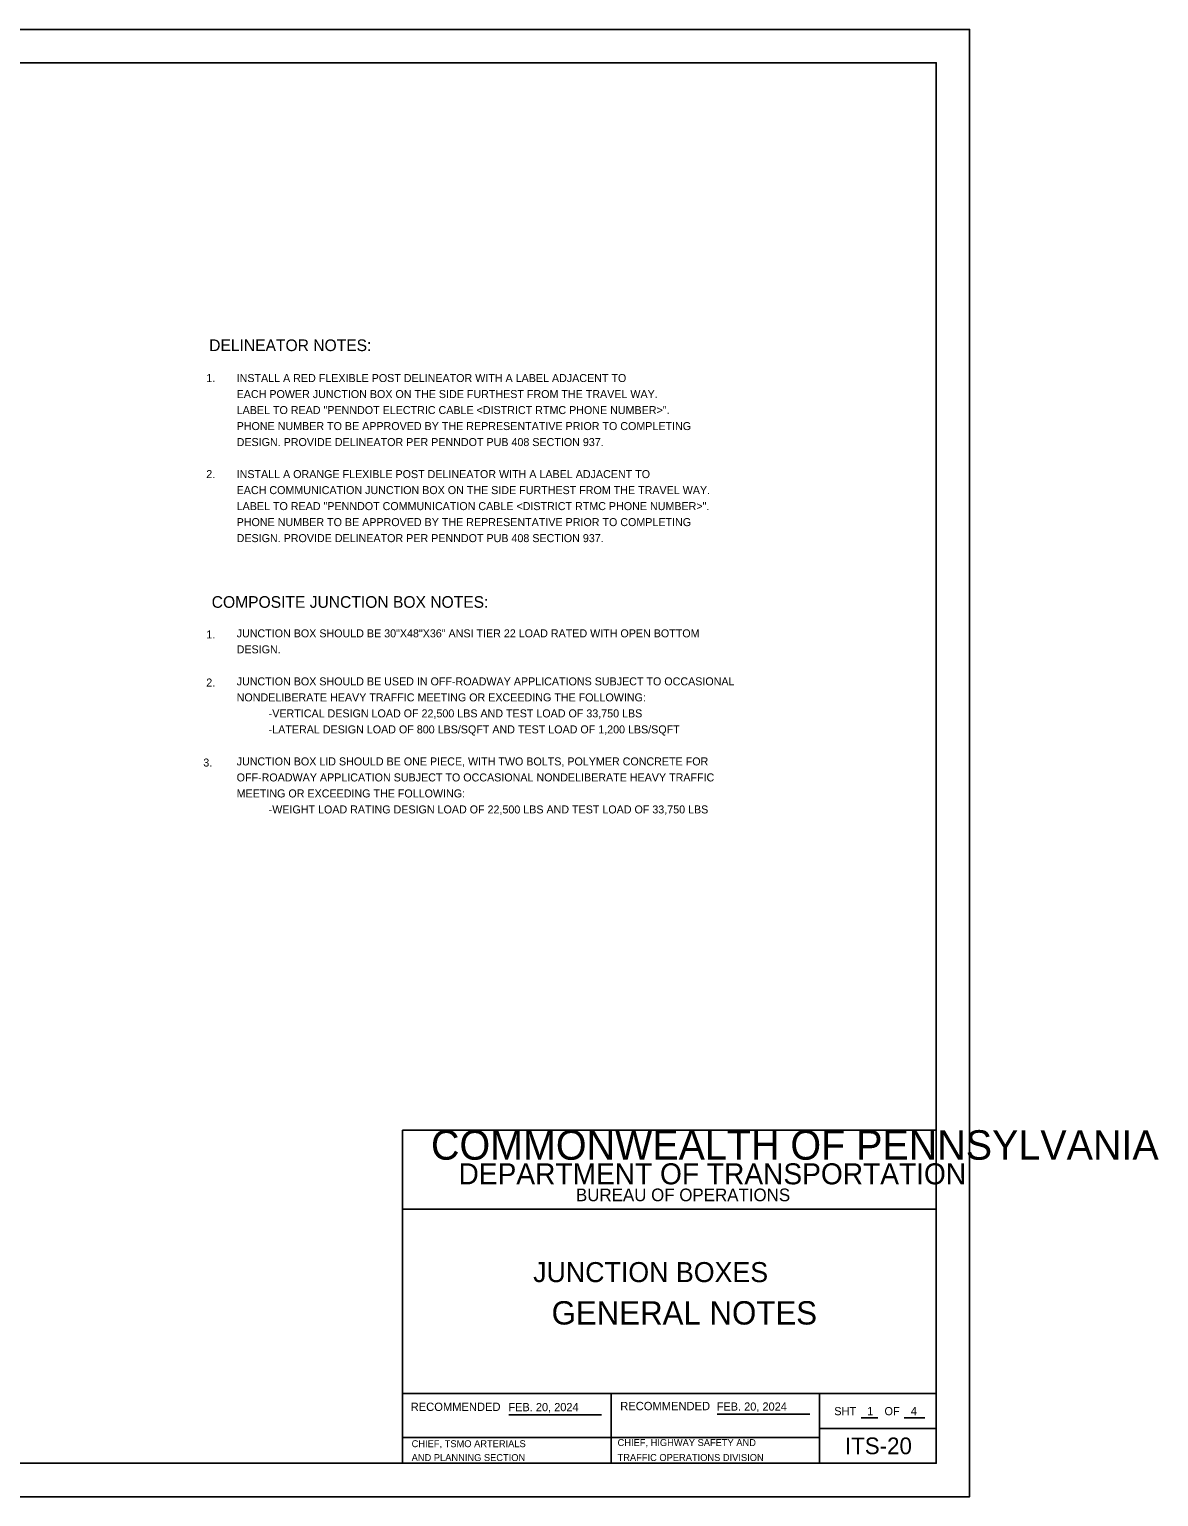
# Model space of a CAD drawing. Extents: x 1299104.8 to 1299141.6, y 239639.8 to 239661.8.
# Drawn here: x 1299124.71 to 1299141.64, y 239639.79 to 239661.79 of the extents above; entities that cross this region are included whole.
import ezdxf

# ---------------------------------------------------------------- set-up
doc = ezdxf.new("R2010")
doc.units = 0
for name, color, linetype in [('1', 7, 'Continuous'), ('2', 7, 'Continuous'), ('DIM TXT', 7, 'Continuous'), ('GS_noplot_1', 7, 'Continuous'), ('GS_plotshape_p', 7, 'Continuous'), ('Level 1', 7, 'Continuous'), ('PTEXT', 7, 'Continuous')]:
    doc.layers.add(name, color=color, linetype=linetype)

msp = doc.modelspace()

# ---------------------------------------------------------------- linework, layer by layer
at = {"layer": '1'}
for p, q in [((1299131.894, 239641.02), (1299133.284, 239641.02)), ((1299135.016, 239641.029), (1299136.405, 239641.029)), ((1299137.176, 239640.973), (1299137.427, 239640.973)), ((1299137.819, 239640.973), (1299138.133, 239640.973)), ((1299130.302, 239640.68), (1299133.427, 239640.68))]:
    msp.add_line(p, q, dxfattribs=at)
at = {"layer": 'GS_noplot_1'}
msp.add_lwpolyline([(1299130.302, 239641.339), (1299136.552, 239641.339), (1299136.552, 239640.291), (1299130.302, 239640.291)], close=True, dxfattribs=at)
at = {"layer": 'GS_plotshape_p'}
msp.add_lwpolyline([(1299104.802, 239661.791), (1299138.802, 239661.791), (1299138.802, 239639.791), (1299104.802, 239639.791)], close=True, dxfattribs=at)
at = {"layer": 'Level 1'}
for p, q in [((1299130.302, 239641.339), (1299138.302, 239641.339)), ((1299133.427, 239641.339), (1299133.427, 239640.291)), ((1299136.552, 239640.815), (1299138.302, 239640.815)), ((1299133.427, 239640.68), (1299136.552, 239640.68))]:
    msp.add_line(p, q, dxfattribs=at)
for points in [[(1299138.302, 239640.291), (1299106.302, 239640.291), (1299106.302, 239661.291), (1299138.302, 239661.291)], [(1299138.302, 239645.284), (1299130.302, 239645.284), (1299130.302, 239644.104), (1299138.302, 239644.104)], [(1299138.302, 239645.284), (1299130.302, 239645.284), (1299130.302, 239640.291), (1299138.302, 239640.291)]]:
    msp.add_lwpolyline(points, close=True, dxfattribs=at)

# ---------------------------------------------------------------- texts
at = {"layer": '1'}
for s, height, p in [('COMMONWEALTH OF PENNSYLVANIA', 0.44223, (1299130.728, 239644.843)), ('DEPARTMENT OF TRANSPORTATION', 0.31514, (1299131.141, 239644.474)), ('BUREAU OF OPERATIONS', 0.18955, (1299132.901, 239644.221)), ('RECOMMENDED', 0.125, (1299130.424, 239641.076)), ('FEB. 20, 2024', 0.12303, (1299131.889, 239641.072)), ('RECOMMENDED', 0.125, (1299133.565, 239641.087)), ('FEB. 20, 2024', 0.12303, (1299135.011, 239641.081)), ('CHIEF, TSMO ARTERIALS ', 0.10417, (1299130.438, 239640.533)), ('CHIEF, HIGHWAY SAFETY AND ', 0.10417, (1299133.525, 239640.55)), ('AND PLANNING SECTION', 0.10417, (1299130.438, 239640.325)), ('TRAFFIC OPERATIONS DIVISION', 0.10417, (1299133.525, 239640.326))]:
    msp.add_text(s, height=height, dxfattribs=at).set_placement(p)
at = {"layer": '2'}
for s, p in [('SHT', (1299136.773, 239641.012)), ('1', (1299137.267, 239641.013)), ('OF', (1299137.526, 239641.012)), ('4', (1299137.921, 239641.013))]:
    msp.add_text(s, height=0.123, dxfattribs=at).set_placement(p)
at = {"layer": 'DIM TXT'}
for s, height, p in [('DELINEATOR NOTES:', 0.175, (1299127.403, 239656.967)), (' 1.', 0.12, (1299127.315, 239656.503)), ('INSTALL A RED FLEXIBLE POST DELINEATOR WITH A LABEL ADJACENT TO ', 0.12, (1299127.815, 239656.503)), ('EACH POWER JUNCTION BOX ON THE SIDE FURTHEST FROM THE TRAVEL WAY. ', 0.12, (1299127.815, 239656.263)), ('LABEL TO READ "PENNDOT ELECTRIC CABLE <DISTRICT RTMC PHONE NUMBER>".', 0.12, (1299127.815, 239656.023)), ('PHONE NUMBER TO BE APPROVED BY THE REPRESENTATIVE PRIOR TO COMPLETING ', 0.12, (1299127.815, 239655.783)), ('DESIGN. PROVIDE DELINEATOR PER PENNDOT PUB 408 SECTION 937.', 0.12, (1299127.815, 239655.543)), (' 2.', 0.12, (1299127.315, 239655.063)), ('INSTALL A ORANGE FLEXIBLE POST DELINEATOR WITH A LABEL ADJACENT TO ', 0.12, (1299127.815, 239655.063)), ('EACH COMMUNICATION JUNCTION BOX ON THE SIDE FURTHEST FROM THE TRAVEL WAY. ', 0.12, (1299127.815, 239654.823)), ('LABEL TO READ "PENNDOT COMMUNICATION CABLE <DISTRICT RTMC PHONE NUMBER>". ', 0.12, (1299127.815, 239654.583)), ('PHONE NUMBER TO BE APPROVED BY THE REPRESENTATIVE PRIOR TO COMPLETING ', 0.12, (1299127.815, 239654.343)), ('DESIGN. PROVIDE DELINEATOR PER PENNDOT PUB 408 SECTION 937.', 0.12, (1299127.815, 239654.103)), ('COMPOSITE JUNCTION BOX NOTES:', 0.175, (1299127.441, 239653.118)), (' 1.', 0.12, (1299127.315, 239652.658)), ('JUNCTION BOX SHOULD BE 30"X48"X36" ANSI TIER 22 LOAD RATED WITH OPEN BOTTOM ', 0.12, (1299127.815, 239652.675)), ('DESIGN.', 0.12, (1299127.815, 239652.435)), (' 2.', 0.12, (1299127.315, 239651.938)), ('JUNCTION BOX SHOULD BE USED IN OFF-ROADWAY APPLICATIONS SUBJECT TO OCCASIONAL ', 0.12, (1299127.815, 239651.955)), ('NONDELIBERATE HEAVY TRAFFIC MEETING OR EXCEEDING THE FOLLOWING:', 0.12, (1299127.815, 239651.715)), ('-VERTICAL DESIGN LOAD OF 22,500 LBS AND TEST LOAD OF 33,750 LBS', 0.12, (1299128.295, 239651.475)), ('-LATERAL DESIGN LOAD OF 800 LBS/SQFT AND TEST LOAD OF 1,200 LBS/SQFT', 0.12, (1299128.295, 239651.235)), ('3.', 0.12, (1299127.315, 239650.738)), ('JUNCTION BOX LID SHOULD BE ONE PIECE, WITH TWO BOLTS, POLYMER CONCRETE FOR ', 0.12, (1299127.815, 239650.755)), ('OFF-ROADWAY APPLICATION SUBJECT TO OCCASIONAL NONDELIBERATE HEAVY TRAFFIC ', 0.12, (1299127.815, 239650.515)), ('MEETING OR EXCEEDING THE FOLLOWING:', 0.12, (1299127.815, 239650.275)), ('-WEIGHT LOAD RATING DESIGN LOAD OF 22,500 LBS AND TEST LOAD OF 33,750 LBS', 0.12, (1299128.295, 239650.035)), ('ITS-20', 0.25, (1299136.934, 239640.428))]:
    msp.add_text(s, height=height, dxfattribs=at).set_placement(p)
at = {"layer": 'PTEXT'}
for s, height, p in [('JUNCTION BOXES', 0.3, (1299132.26, 239643.008)), ('GENERAL NOTES', 0.35, (1299132.536, 239642.372))]:
    msp.add_text(s, height=height, dxfattribs=at).set_placement(p)

doc.saveas('drawing.dxf')
